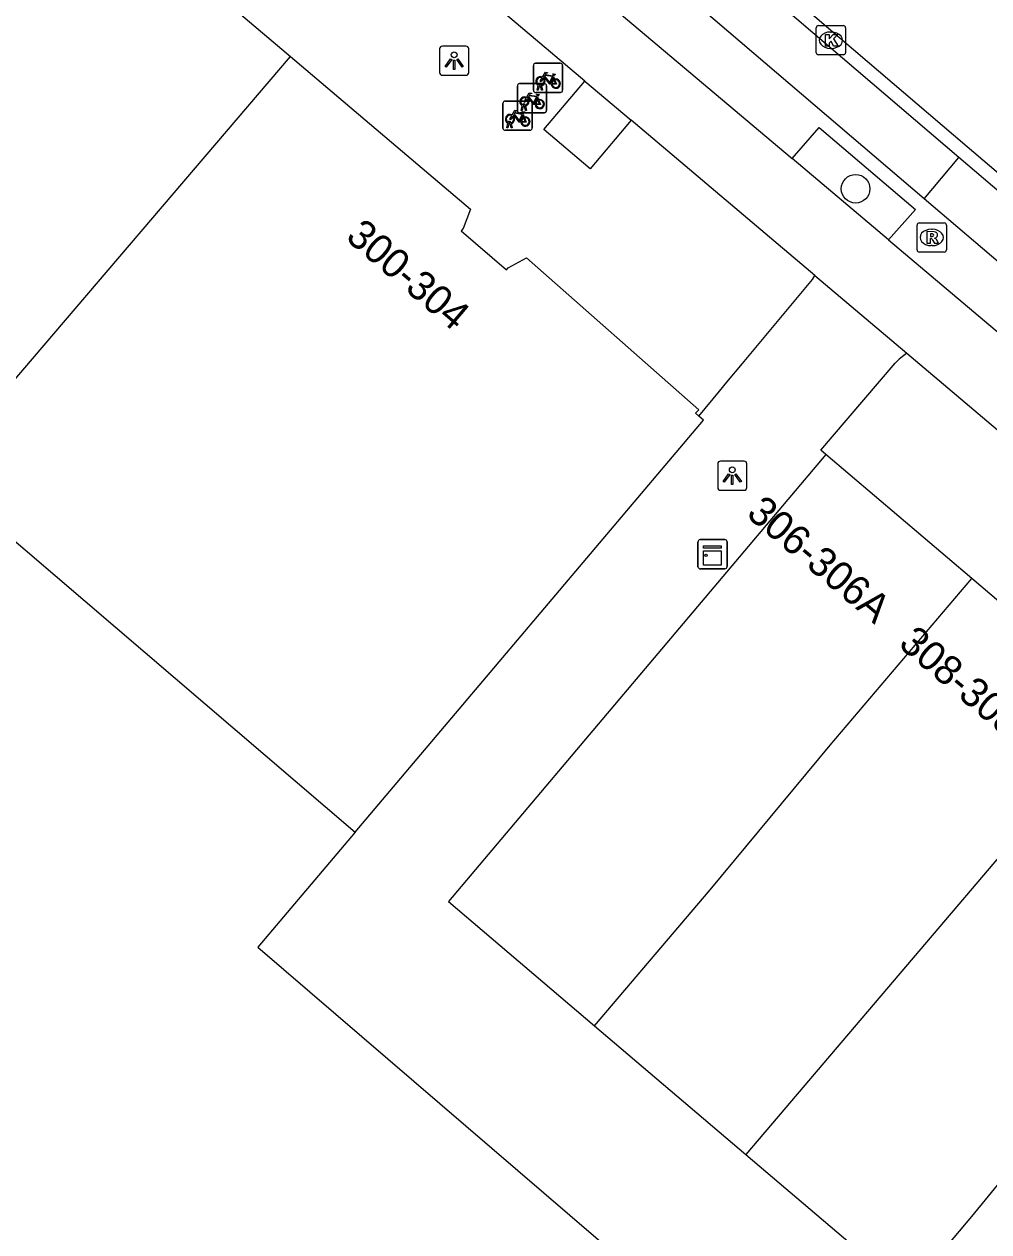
# Model space of a CAD drawing. Extents: x 162347 to 162868, y 381221 to 381813.
# Drawn here: x 162770.22 to 162803.24, y 381536.21 to 381577.53 of the extents above; entities that cross this region are included whole.
import ezdxf

# ---------------------------------------------------------------- set-up
doc = ezdxf.new("R2010")
doc.units = 0
for name, color, linetype in [('IMGEO_Berm_open', 7, 'Continuous'), ('IMGEO_Boom', 7, 'Continuous'), ('IMGEO_Fietsenrek', 7, 'Continuous'), ('IMGEO_Fietspad_gesloten', 7, 'Continuous'), ('IMGEO_Kast', 7, 'Continuous'), ('IMGEO_Kolk', 7, 'Continuous'), ('IMGEO_Lichtpunt', 7, 'Continuous'), ('IMGEO_Pand', 7, 'Continuous'), ('IMGEO_Pand_nummerreeks', 7, 'Continuous'), ('IMGEO_Parkeervlak_open', 7, 'Continuous'), ('IMGEO_Rijbaan_lokaal_gesloten', 7, 'Continuous'), ('IMGEO_Rijbaan_lokaal_open', 7, 'Continuous'), ('IMGEO_Rioolput', 7, 'Continuous'), ('IMGEO_Voetpad_open', 7, 'Continuous')]:
    doc.layers.add(name, color=color, linetype=linetype)

msp = doc.modelspace()

# ---------------------------------------------------------------- linework, layer by layer
at = {"layer": 'IMGEO_Berm_open'}
for points in [[(162796.513, 381572.933), (162797.434, 381573.995), (162800.73, 381571.194), (162799.811, 381570.151)], [(162805.642, 381567.628), (162801.035, 381571.562)]]:
    msp.add_lwpolyline(points, dxfattribs=at)
at = {"layer": 'IMGEO_Boom'}
msp.add_circle((162798.684, 381571.9), 0.489, dxfattribs=at)
at = {"layer": 'IMGEO_Fietsenrek'}
for p, q in [((162787.656, 381575.271), (162787.656, 381576.112)), ((162787.656, 381576.112), (162787.656, 381575.271)), ((162787.731, 381576.196), (162788.572, 381576.196)), ((162788.572, 381576.196), (162787.731, 381576.196)), ((162788.656, 381576.121), (162788.656, 381575.28)), ((162788.656, 381575.28), (162788.656, 381576.121)), ((162788.343, 381575.745), (162788.379, 381575.65)), ((162787.106, 381574.573), (162787.106, 381575.414)), ((162787.106, 381575.414), (162787.106, 381574.573)), ((162787.181, 381575.498), (162788.022, 381575.498)), ((162788.022, 381575.498), (162787.181, 381575.498)), ((162788.581, 381575.196), (162787.74, 381575.196)), ((162787.74, 381575.196), (162788.581, 381575.196)), ((162787.783, 381575.28), (162787.822, 381575.44)), ((162787.817, 381575.28), (162787.783, 381575.28)), ((162787.852, 381575.428), (162787.817, 381575.28)), ((162787.894, 381575.452), (162787.893, 381575.456)), ((162787.935, 381575.28), (162787.901, 381575.422)), ((162787.925, 381575.463), (162787.926, 381575.456)), ((162787.933, 381575.426), (162787.968, 381575.28)), ((162787.968, 381575.28), (162787.935, 381575.28)), ((162788.106, 381575.423), (162788.106, 381574.582)), ((162788.106, 381574.582), (162788.106, 381575.423)), ((162786.614, 381573.976), (162786.614, 381574.817)), ((162786.614, 381574.817), (162786.614, 381573.976)), ((162786.689, 381574.901), (162787.53, 381574.901)), ((162787.53, 381574.901), (162786.689, 381574.901)), ((162787.344, 381574.754), (162787.343, 381574.758)), ((162787.375, 381574.765), (162787.376, 381574.758)), ((162787.614, 381574.826), (162787.614, 381573.985)), ((162787.614, 381573.985), (162787.614, 381574.826)), ((162787.793, 381575.047), (162787.829, 381574.952)), ((162788.031, 381574.498), (162787.19, 381574.498)), ((162787.19, 381574.498), (162788.031, 381574.498)), ((162787.233, 381574.582), (162787.272, 381574.742)), ((162787.267, 381574.582), (162787.233, 381574.582)), ((162787.302, 381574.73), (162787.267, 381574.582)), ((162787.301, 381574.45), (162787.337, 381574.355)), ((162787.385, 381574.582), (162787.351, 381574.724)), ((162787.383, 381574.728), (162787.418, 381574.582)), ((162787.418, 381574.582), (162787.385, 381574.582)), ((162786.741, 381573.985), (162786.78, 381574.145)), ((162786.775, 381573.985), (162786.741, 381573.985)), ((162786.81, 381574.133), (162786.775, 381573.985)), ((162786.852, 381574.157), (162786.851, 381574.161)), ((162786.893, 381573.985), (162786.859, 381574.127)), ((162786.883, 381574.168), (162786.884, 381574.161)), ((162786.891, 381574.131), (162786.926, 381573.985)), ((162786.926, 381573.985), (162786.893, 381573.985)), ((162787.539, 381573.901), (162786.698, 381573.901)), ((162786.698, 381573.901), (162787.539, 381573.901))]:
    msp.add_line(p, q, dxfattribs=at)
for points in [[(162787.99, 381575.67), (162787.938, 381575.58), (162787.898, 381575.555), (162787.899, 381575.602), (162787.954, 381575.696)], [(162787.969, 381575.722), (162788.064, 381575.886), (162788.15, 381575.872), (162788.152, 381575.863), (162788.096, 381575.852), (162788.069, 381575.807), (162788.325, 381575.766)], [(162788.265, 381575.478), (162788.215, 381575.478), (162788.024, 381575.729), (162788.005, 381575.697)], [(162788.312, 381575.741), (162788.055, 381575.782), (162788.038, 381575.753), (162788.205, 381575.533), (162788.312, 381575.741)], [(162788.36, 381575.643), (162788.33, 381575.72), (162788.221, 381575.502), (162788.264, 381575.502)], [(162788.294, 381575.502), (162788.414, 381575.501), (162788.37, 381575.615)], [(162788.39, 381575.622), (162788.445, 381575.477), (162788.295, 381575.477)], [(162788.325, 381575.766), (162788.35, 381575.815), (162788.344, 381575.819), (162788.321, 381575.823), (162788.309, 381575.83), (162788.308, 381575.833), (162788.31, 381575.838), (162788.405, 381575.823), (162788.407, 381575.813), (162788.397, 381575.8), (162788.385, 381575.794), (162788.371, 381575.8), (162788.343, 381575.745)], [(162787.419, 381575.024), (162787.514, 381575.188), (162787.6, 381575.174), (162787.602, 381575.165), (162787.546, 381575.154), (162787.519, 381575.109), (162787.775, 381575.068)], [(162787.44, 381574.972), (162787.388, 381574.882), (162787.348, 381574.857), (162787.349, 381574.904), (162787.404, 381574.998)], [(162787.715, 381574.78), (162787.665, 381574.78), (162787.474, 381575.031), (162787.455, 381574.999)], [(162787.762, 381575.043), (162787.505, 381575.084), (162787.488, 381575.055), (162787.655, 381574.835), (162787.762, 381575.043)], [(162787.81, 381574.945), (162787.78, 381575.022), (162787.671, 381574.804), (162787.714, 381574.804)], [(162787.744, 381574.804), (162787.864, 381574.803), (162787.82, 381574.917)], [(162787.84, 381574.924), (162787.895, 381574.779), (162787.745, 381574.779)], [(162787.775, 381575.068), (162787.8, 381575.117), (162787.794, 381575.121), (162787.771, 381575.125), (162787.759, 381575.132), (162787.758, 381575.135), (162787.76, 381575.14), (162787.855, 381575.125), (162787.857, 381575.115), (162787.847, 381575.102), (162787.835, 381575.096), (162787.821, 381575.102), (162787.793, 381575.047)], [(162786.948, 381574.375), (162786.896, 381574.285), (162786.856, 381574.26), (162786.857, 381574.307), (162786.912, 381574.401)], [(162786.927, 381574.427), (162787.022, 381574.591), (162787.108, 381574.577), (162787.11, 381574.568), (162787.054, 381574.557), (162787.027, 381574.512), (162787.283, 381574.471)], [(162787.223, 381574.183), (162787.173, 381574.183), (162786.982, 381574.434), (162786.963, 381574.402)], [(162787.27, 381574.446), (162787.013, 381574.487), (162786.996, 381574.458), (162787.163, 381574.238), (162787.27, 381574.446)], [(162787.318, 381574.348), (162787.288, 381574.425), (162787.179, 381574.207), (162787.222, 381574.207)], [(162787.283, 381574.471), (162787.308, 381574.52), (162787.302, 381574.524), (162787.279, 381574.528), (162787.267, 381574.535), (162787.266, 381574.538), (162787.268, 381574.543), (162787.363, 381574.528), (162787.365, 381574.518), (162787.355, 381574.505), (162787.343, 381574.499), (162787.329, 381574.505), (162787.301, 381574.45)], [(162787.252, 381574.207), (162787.372, 381574.206), (162787.328, 381574.32)], [(162787.348, 381574.327), (162787.403, 381574.182), (162787.253, 381574.182)]]:
    msp.add_lwpolyline(points, dxfattribs=at)
for centre, radius, start, end in [((162787.734, 381576.118), 0.0779, 92.4484, 184.2845), ((162787.734, 381576.118), 0.0779, 92.4484, 184.2845), ((162788.578, 381576.118), 0.0779, 2.4484, 94.2845), ((162788.578, 381576.118), 0.0779, 2.4484, 94.2845), ((162787.896, 381575.581), 0.159, 62.6766, 242.1369), ((162787.896, 381575.581), 0.129, 63.3192, 238.903), ((162787.896, 381575.581), 0.129, 283.6043, 43.4302), ((162787.896, 381575.581), 0.159, 283.5766, 46.6042), ((162788.423, 381575.497), 0.159, 113.3408, 178.3217), ((162788.423, 381575.497), 0.159, 187.0065, 105.7708), ((162788.423, 381575.497), 0.129, 113.923, 177.9556), ((162788.423, 381575.497), 0.129, 188.6715, 104.5883), ((162787.184, 381575.42), 0.0779, 92.4484, 184.2845), ((162787.184, 381575.42), 0.0779, 92.4484, 184.2845), ((162787.734, 381575.274), 0.0779, 182.4484, 274.2845), ((162787.734, 381575.274), 0.0779, 182.4484, 274.2845), ((162787.876, 381575.452), 0.0499, 12.8025, 158.6934), ((162787.896, 381575.581), 0.159, 253.9967, 271.7867), ((162787.876, 381575.452), 0.0174, 12.8025, 163.4502), ((162787.896, 381575.581), 0.129, 253.415, 269.0204), ((162788.028, 381575.42), 0.0779, 2.4484, 94.2845), ((162788.028, 381575.42), 0.0779, 2.4484, 94.2845), ((162788.578, 381575.274), 0.0779, 272.4484, 4.2845), ((162788.578, 381575.274), 0.0779, 272.4484, 4.2845), ((162786.692, 381574.823), 0.0779, 92.4484, 184.2845), ((162786.692, 381574.823), 0.0779, 92.4484, 184.2845), ((162787.346, 381574.883), 0.159, 62.6766, 242.1369), ((162787.346, 381574.883), 0.129, 63.3192, 238.903), ((162787.326, 381574.754), 0.0499, 12.8025, 158.6934), ((162787.326, 381574.754), 0.0174, 12.8025, 163.4502), ((162787.346, 381574.883), 0.129, 253.415, 269.0204), ((162787.346, 381574.883), 0.129, 283.6043, 43.4302), ((162787.346, 381574.883), 0.159, 283.5766, 46.6042), ((162787.536, 381574.823), 0.0779, 2.4484, 94.2845), ((162787.536, 381574.823), 0.0779, 2.4484, 94.2845), ((162787.873, 381574.799), 0.159, 113.3408, 178.3217), ((162787.873, 381574.799), 0.159, 187.0065, 105.7708), ((162787.873, 381574.799), 0.129, 113.923, 177.9556), ((162787.873, 381574.799), 0.129, 188.6715, 104.5883), ((162786.854, 381574.286), 0.159, 62.6766, 242.1369), ((162786.854, 381574.286), 0.129, 63.3192, 238.903), ((162786.854, 381574.286), 0.129, 283.6043, 43.4302), ((162786.854, 381574.286), 0.159, 283.5766, 46.6042), ((162787.184, 381574.576), 0.0779, 182.4484, 274.2845), ((162787.184, 381574.576), 0.0779, 182.4484, 274.2845), ((162787.381, 381574.202), 0.159, 113.3408, 178.3217), ((162787.381, 381574.202), 0.159, 187.0065, 105.7708), ((162787.346, 381574.883), 0.159, 253.9967, 271.7867), ((162788.028, 381574.576), 0.0779, 272.4484, 4.2845), ((162788.028, 381574.576), 0.0779, 272.4484, 4.2845), ((162786.692, 381573.979), 0.0779, 182.4484, 274.2845), ((162786.692, 381573.979), 0.0779, 182.4484, 274.2845), ((162786.834, 381574.157), 0.0499, 12.8025, 158.6934), ((162786.854, 381574.286), 0.159, 253.9967, 271.7867), ((162786.834, 381574.157), 0.0174, 12.8025, 163.4502), ((162786.854, 381574.286), 0.129, 253.415, 269.0204), ((162787.381, 381574.202), 0.129, 113.923, 177.9556), ((162787.381, 381574.202), 0.129, 188.6715, 104.5883), ((162787.536, 381573.979), 0.0779, 272.4484, 4.2845), ((162787.536, 381573.979), 0.0779, 272.4484, 4.2845)]:
    msp.add_arc(centre, radius, start, end, dxfattribs=at)
at = {"layer": 'IMGEO_Fietspad_gesloten'}
for points in [[(162789.414, 381575.587), (162776.8, 381586.246)], [(162782.289, 381584.929), (162796.513, 381572.933)], [(162789.414, 381575.587), (162791.002, 381574.245)], [(162797.286, 381568.935), (162791.002, 381574.245)], [(162799.811, 381570.151), (162796.513, 381572.933)], [(162799.811, 381570.151), (162817.483, 381555.246)], [(162800.436, 381566.273), (162829.055, 381542.09), (162840.499, 381532.368)]]:
    msp.add_lwpolyline(points, dxfattribs=at)
at = {"layer": 'IMGEO_Kast'}
for p, q in [((162793.361, 381559.895), (162794.202, 381559.895)), ((162794.202, 381559.895), (162793.361, 381559.895)), ((162793.286, 381558.97), (162793.286, 381559.811)), ((162793.286, 381559.811), (162793.286, 381558.97)), ((162794.286, 381559.82), (162794.286, 381558.979)), ((162794.286, 381558.979), (162794.286, 381559.82)), ((162794.211, 381558.895), (162793.37, 381558.895)), ((162793.37, 381558.895), (162794.211, 381558.895))]:
    msp.add_line(p, q, dxfattribs=at)
for points in [[(162793.481, 381559.685), (162794.081, 381559.685), (162794.081, 381559.6), (162793.481, 381559.6), (162793.481, 381559.685)], [(162793.481, 381559.51), (162794.081, 381559.51), (162794.081, 381559.021), (162793.481, 381559.021), (162793.481, 381559.51)]]:
    msp.add_lwpolyline(points, dxfattribs=at)
msp.add_circle((162793.565, 381559.359), 0.0377, dxfattribs=at)
for centre, start, end in [((162793.364, 381559.817), 92.4484, 184.2845), ((162793.364, 381559.817), 92.4484, 184.2845), ((162794.208, 381559.817), 2.4484, 94.2845), ((162794.208, 381559.817), 2.4484, 94.2845), ((162793.364, 381558.973), 182.4484, 274.2845), ((162793.364, 381558.973), 182.4484, 274.2845), ((162794.208, 381558.973), 272.4484, 4.2845), ((162794.208, 381558.973), 272.4484, 4.2845)]:
    msp.add_arc(centre, 0.0779, start, end, dxfattribs=at)
at = {"layer": 'IMGEO_Kolk'}
for p, q in [((162797.337, 381576.558), (162797.337, 381577.41)), ((162797.412, 381577.484), (162798.264, 381577.484)), ((162797.825, 381577.264), (162797.85, 381577.264)), ((162798.338, 381577.41), (162798.338, 381576.558)), ((162798.264, 381576.484), (162797.412, 381576.484)), ((162797.848, 381576.704), (162797.823, 381576.704))]:
    msp.add_line(p, q, dxfattribs=at)
for points in [[(162797.337, 381576.558), (162797.337, 381577.41)], [(162797.412, 381577.484), (162798.264, 381577.484)], [(162798.338, 381577.41), (162798.338, 381576.558)], [(162797.658, 381577.184), (162797.781, 381577.184), (162797.781, 381577.033), (162797.911, 381577.184), (162798.075, 381577.184), (162797.929, 381577.033), (162798.082, 381576.784), (162797.93, 381576.784), (162797.845, 381576.948), (162797.781, 381576.881), (162797.781, 381576.784), (162797.658, 381576.784), (162797.658, 381577.184)], [(162798.264, 381576.484), (162797.412, 381576.484)]]:
    msp.add_lwpolyline(points, dxfattribs=at)
for centre, start, end in [((162797.414, 381577.408), 91.552, 178.448), ((162797.414, 381577.408), 91.552, 178.448), ((162798.262, 381577.408), 1.552, 88.448), ((162798.262, 381577.408), 1.552, 88.448), ((162797.414, 381576.56), 181.552, 268.448), ((162797.414, 381576.56), 181.552, 268.448), ((162798.262, 381576.56), 271.552, 358.448), ((162798.262, 381576.56), 271.552, 358.448)]:
    msp.add_arc(centre, 0.0765, start, end, dxfattribs=at)
for centre, major_axis, ratio, start_param, end_param in [((162797.824, 381576.984), (-0.387, 0.002), 0.722429, 4.712389, 7.853982), ((162797.849, 381576.984), (-0.39, 0.002), 0.717154, 1.570796, 4.712389)]:
    msp.add_ellipse(centre, major_axis=major_axis, ratio=ratio, start_param=start_param, end_param=end_param, dxfattribs=at)
at = {"layer": 'IMGEO_Lichtpunt'}
for p, q in [((162784.445, 381576.687), (162784.445, 381575.88)), ((162784.445, 381576.687), (162784.445, 381575.88)), ((162785.347, 381576.782), (162784.539, 381576.782)), ((162785.347, 381576.782), (162784.539, 381576.782)), ((162785.441, 381575.88), (162785.441, 381576.687)), ((162785.441, 381575.88), (162785.441, 381576.687)), ((162784.539, 381575.786), (162785.347, 381575.786)), ((162784.539, 381575.786), (162785.347, 381575.786)), ((162793.964, 381562.486), (162793.964, 381561.679)), ((162793.964, 381562.486), (162793.964, 381561.679)), ((162794.866, 381562.581), (162794.058, 381562.581)), ((162794.866, 381562.581), (162794.058, 381562.581)), ((162794.96, 381561.679), (162794.96, 381562.486)), ((162794.96, 381561.679), (162794.96, 381562.486)), ((162794.058, 381561.585), (162794.866, 381561.585)), ((162794.058, 381561.585), (162794.866, 381561.585))]:
    msp.add_line(p, q, dxfattribs=at)
for points in [[(162784.819, 381576.351), (162784.858, 381576.323), (162784.67, 381576.061), (162784.632, 381576.088), (162784.819, 381576.351)], [(162784.921, 381576.303), (162784.968, 381576.303), (162784.968, 381575.981), (162784.921, 381575.981), (162784.921, 381576.303)], [(162785.031, 381576.323), (162785.069, 381576.35), (162785.256, 381576.088), (162785.217, 381576.06), (162785.031, 381576.323)], [(162794.338, 381562.15), (162794.377, 381562.122), (162794.189, 381561.86), (162794.151, 381561.887), (162794.338, 381562.15)], [(162794.44, 381562.102), (162794.487, 381562.102), (162794.487, 381561.78), (162794.44, 381561.78), (162794.44, 381562.102)], [(162794.55, 381562.122), (162794.588, 381562.149), (162794.775, 381561.887), (162794.736, 381561.859), (162794.55, 381562.122)]]:
    msp.add_lwpolyline(points, dxfattribs=at)
for centre in [(162784.944, 381576.485), (162794.463, 381562.284)]:
    msp.add_circle(centre, 0.0994, dxfattribs=at)
for centre, start, end in [((162784.539, 381576.687), 90, 180), ((162784.539, 381576.687), 90, 180), ((162785.347, 381576.687), 0, 90), ((162785.347, 381576.687), 0, 90), ((162784.539, 381575.88), 180, 270), ((162784.539, 381575.88), 180, 270), ((162785.347, 381575.88), 270, 0), ((162785.347, 381575.88), 270, 360), ((162794.058, 381562.486), 90, 180), ((162794.058, 381562.486), 90, 180), ((162794.866, 381562.486), 0, 90), ((162794.866, 381562.486), 0, 90), ((162794.058, 381561.679), 180, 270), ((162794.058, 381561.679), 180, 270), ((162794.866, 381561.679), 270, 0), ((162794.866, 381561.679), 270, 360)]:
    msp.add_arc(centre, 0.0946, start, end, dxfattribs=at)
at = {"layer": 'IMGEO_Pand'}
for points in [[(162767.108, 381586.816), (162771.066, 381583.46), (162770.962, 381582.466), (162770.754, 381582.237), (162772.35, 381580.9), (162772.583, 381581.146), (162773.505, 381581.378), (162779.344, 381576.422)], [(162767.974, 381563.126), (162779.344, 381576.422)], [(162779.344, 381576.422), (162785.499, 381571.198), (162785.248, 381570.543), (162785.183, 381570.467), (162786.735, 381569.128), (162786.794, 381569.196), (162787.421, 381569.54), (162793.318, 381564.342), (162793.209, 381564.218), (162793.314, 381564.125)], [(162781.551, 381549.885), (162793.475, 381563.984), (162793.314, 381564.125)], [(162767.974, 381563.126), (162767.164, 381562.178), (162781.551, 381549.885)], [(162797.667, 381562.809), (162789.569, 381553.221), (162784.745, 381547.512), (162789.745, 381543.262)], [(162802.659, 381558.563), (162797.667, 381562.809)], [(162789.745, 381543.262), (162793.7, 381547.913), (162797.816, 381552.864), (162802.659, 381558.563)], [(162807.896, 381554.107), (162802.659, 381558.563)], [(162807.896, 381554.107), (162803.056, 381548.411), (162794.922, 381538.86)], [(162781.551, 381549.885), (162778.227, 381545.954), (162796.917, 381529.909), (162796.986, 381529.991)], [(162813.298, 381549.512), (162808.46, 381543.819), (162802.645, 381536.74), (162800.467, 381534.147)], [(162789.745, 381543.262), (162794.922, 381538.86)], [(162794.922, 381538.86), (162800.467, 381534.147)]]:
    msp.add_lwpolyline(points, dxfattribs=at)
at = {"layer": 'IMGEO_Parkeervlak_open'}
for points in [[(162801.035, 381571.562), (162759.969, 381606.584), (162761.128, 381608.048)], [(162801.035, 381571.562), (162802.217, 381572.973)]]:
    msp.add_lwpolyline(points, dxfattribs=at)
at = {"layer": 'IMGEO_Rijbaan_lokaal_gesloten'}
msp.add_lwpolyline([(162761.412, 381608.404), (162802.506, 381573.344), (162829.77, 381550.157), (162832.081, 381548.137)], dxfattribs=at)
at = {"layer": 'IMGEO_Rijbaan_lokaal_open'}
for points in [[(162802.217, 381572.973), (162761.128, 381608.048)], [(162806.751, 381569.117), (162802.217, 381572.973)], [(162793.314, 381564.125), (162794.023, 381564.977), (162794.279, 381565.284), (162794.81, 381565.922), (162797.204, 381568.799), (162797.286, 381568.935)], [(162797.286, 381568.935), (162800.436, 381566.273)], [(162797.667, 381562.809), (162797.494, 381562.956), (162797.896, 381563.425), (162800.041, 381565.929)]]:
    msp.add_lwpolyline(points, dxfattribs=at)
msp.add_arc((162801.646, 381564.485), 2.159, 124.084, 138.0203, dxfattribs=at)
at = {"layer": 'IMGEO_Rioolput'}
for p, q in [((162800.789, 381569.809), (162800.789, 381570.661)), ((162800.864, 381570.735), (162801.716, 381570.735)), ((162801.79, 381570.661), (162801.79, 381569.809)), ((162801.277, 381570.515), (162801.302, 381570.515)), ((162801.3, 381569.955), (162801.275, 381569.955)), ((162801.716, 381569.735), (162800.864, 381569.735))]:
    msp.add_line(p, q, dxfattribs=at)
for points in [[(162800.789, 381569.809), (162800.789, 381570.661)], [(162800.864, 381570.735), (162801.716, 381570.735)], [(162801.79, 381570.661), (162801.79, 381569.809)], [(162801.378, 381570.433), (162801.126, 381570.435), (162801.126, 381570.035)], [(162801.304, 381570.354), (162801.25, 381570.354), (162801.25, 381570.273)], [(162801.25, 381570.273), (162801.302, 381570.273)], [(162801.126, 381570.035), (162801.25, 381570.035), (162801.25, 381570.197), (162801.261, 381570.197)], [(162801.308, 381570.168), (162801.379, 381570.035), (162801.519, 381570.035), (162801.454, 381570.161)], [(162801.716, 381569.735), (162800.864, 381569.735)]]:
    msp.add_lwpolyline(points, dxfattribs=at)
for centre, radius, start, end in [((162800.866, 381570.659), 0.0765, 91.552, 178.448), ((162800.866, 381570.659), 0.0765, 91.552, 178.448), ((162801.714, 381570.659), 0.0765, 1.552, 88.448), ((162801.714, 381570.659), 0.0765, 1.552, 88.448), ((162801.286, 381570.462), 0.19, 274.7715, 282.9687), ((162801.31, 381570.258), 0.0964, 77.0061, 93.1865), ((162801.324, 381570.315), 0.0378, 276.6634, 79.6772), ((162801.377, 381570.323), 0.109, 350.3612, 89.416), ((162801.375, 381570.323), 0.112, 277.5842, 350.9817), ((162801.359, 381570.108), 0.108, 29.5134, 73.7905), ((162800.866, 381569.811), 0.0765, 181.552, 268.448), ((162800.866, 381569.811), 0.0765, 181.552, 268.448), ((162801.26, 381570.144), 0.0533, 26.0293, 88.6989), ((162801.714, 381569.811), 0.0765, 271.552, 358.448), ((162801.714, 381569.811), 0.0765, 271.552, 358.448)]:
    msp.add_arc(centre, radius, start, end, dxfattribs=at)
for centre, major_axis, ratio, start_param, end_param in [((162801.276, 381570.235), (-0.387, 0.002), 0.722429, 4.712389, 7.853982), ((162801.301, 381570.235), (-0.39, 0.002), 0.717154, 1.570796, 4.712389)]:
    msp.add_ellipse(centre, major_axis=major_axis, ratio=ratio, start_param=start_param, end_param=end_param, dxfattribs=at)
at = {"layer": 'IMGEO_Voetpad_open'}
msp.add_lwpolyline([(162791.002, 381574.245), (162789.596, 381572.578), (162788.01, 381573.924), (162789.414, 381575.587)], dxfattribs=at)

# ---------------------------------------------------------------- texts
at = {"layer": 'IMGEO_Pand_nummerreeks'}
for s, rotation, p in [('300-304', 319.4632, (162781.19, 381570.187)), ('306-306A', 319.8815, (162794.905, 381560.716)), ('308-308A', 319.6523, (162800.111, 381556.262))]:
    msp.add_text(s, height=1, rotation=rotation, dxfattribs=at).set_placement(p)

doc.saveas('drawing.dxf')
